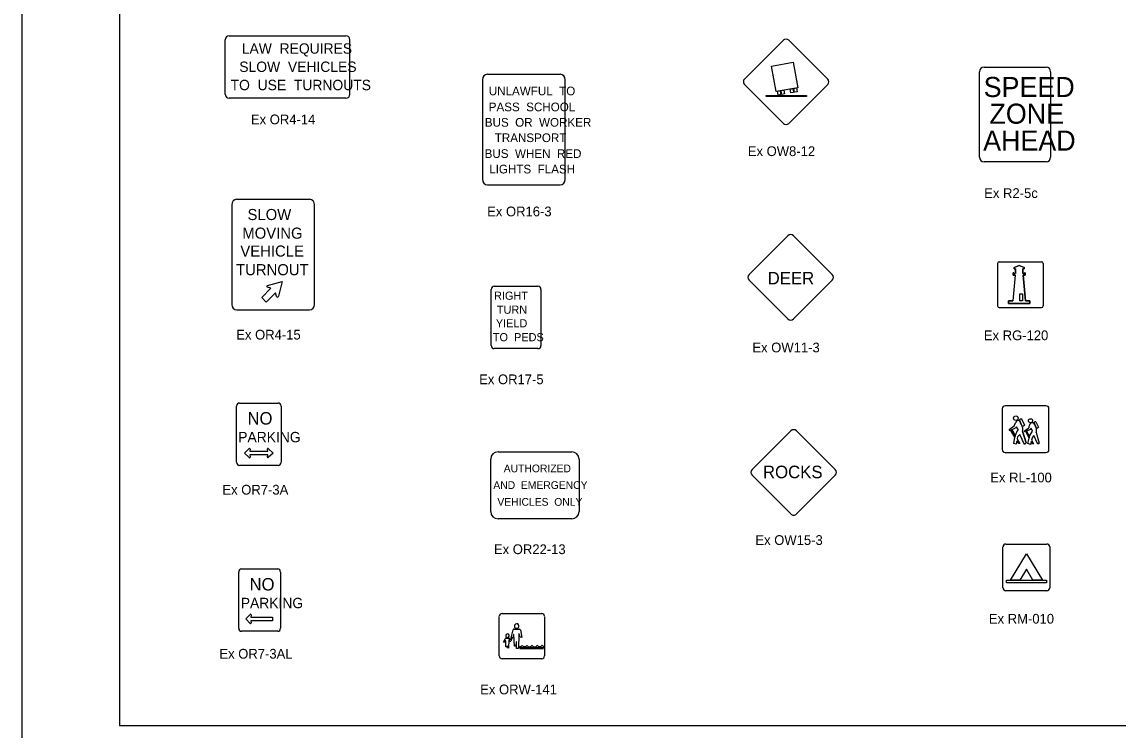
# Model space of a CAD drawing. Extents: x 42133 to 45533, y 41351 to 47951.
# Drawn here: x 42133 to 42977, y 45798 to 46343 of the extents above; entities that cross this region are included whole.
import ezdxf

# ---------------------------------------------------------------- set-up
doc = ezdxf.new("R2010")
doc.units = 0
for name, color, linetype in [('#plot_shape', 7, 'Continuous'), ('P_ODOT_PLAN_Border', 7, 'Continuous'), ('P_TRAF_SIGN_SignDetails', 7, 'Continuous')]:
    doc.layers.add(name, color=color, linetype=linetype)

msp = doc.modelspace()

# ---------------------------------------------------------------- linework, layer by layer
at = {"layer": '#plot_shape'}
msp.add_lwpolyline([(42133.34, 45751.35), (43833.34, 45751.35), (43833.34, 46851.35), (42133.34, 46851.35)], close=True, dxfattribs=at)
at = {"layer": 'P_ODOT_PLAN_Border'}
msp.add_lwpolyline([(42208.34, 45801.35), (43808.34, 45801.35), (43808.34, 46801.35), (42208.34, 46801.35)], close=True, dxfattribs=at)
at = {"layer": 'P_TRAF_SIGN_SignDetails'}
for p, q in [((42292.85, 46332.06), (42382.79, 46332.06)), ((42289.86, 46287.1), (42289.86, 46329.08)), ((42385.78, 46287.1), (42385.78, 46329.08)), ((42719.43, 46328.7), (42689.55, 46298.84)), ((42753.57, 46298.84), (42723.69, 46328.7)), ((42873.93, 46308.08), (42921.76, 46308.08)), ((42487.83, 46298.27), (42487.83, 46221.7)), ((42491.82, 46302.52), (42547.63, 46302.52)), ((42551.61, 46221.7), (42551.61, 46298.27)), ((42870.51, 46238.81), (42870.51, 46304.43)), ((42925.18, 46304.43), (42925.18, 46238.81)), ((42689.55, 46294.57), (42719.43, 46264.69)), ((42723.69, 46264.69), (42753.57, 46294.57)), ((42382.79, 46284.23), (42292.85, 46284.23)), ((42921.76, 46235.16), (42873.93, 46235.16)), ((42491.82, 46217.45), (42547.63, 46217.45)), ((42298.8, 46206.26), (42354.61, 46206.26)), ((42294.8, 46202), (42294.8, 46125.43)), ((42358.59, 46125.43), (42358.59, 46202)), ((42722.91, 46178.18), (42693.03, 46148.29)), ((42757.05, 46148.29), (42727.17, 46178.18)), ((42884.29, 46156.88), (42884.29, 46124.29)), ((42885.65, 46158.22), (42918.16, 46158.22)), ((42897.12, 46153.71), (42900.94, 46155.39)), ((42897.12, 46152.69), (42897.12, 46153.71)), ((42897.12, 46152.69), (42897.12, 46153.71)), ((42897.12, 46152.69), (42897.12, 46153.71)), ((42900.94, 46155.39), (42904.75, 46153.71)), ((42904.75, 46153.71), (42904.75, 46152.69)), ((42904.75, 46153.71), (42904.75, 46152.69)), ((42904.75, 46153.71), (42904.75, 46152.69)), ((42919.52, 46156.85), (42919.52, 46124.35)), ((42896.25, 46149.64), (42896.76, 46149.64)), ((42896.25, 46147.91), (42896.25, 46149.64)), ((42897.78, 46147.91), (42896.25, 46147.91)), ((42896.76, 46149.64), (42896.76, 46149.18)), ((42896.76, 46149.18), (42898.03, 46149.18)), ((42898.03, 46152.69), (42897.12, 46152.69)), ((42898.03, 46149.18), (42898.03, 46152.69)), ((42904.75, 46152.69), (42903.84, 46152.69)), ((42903.84, 46152.69), (42903.84, 46149.18)), ((42903.84, 46149.18), (42905.11, 46149.18)), ((42904.09, 46147.91), (42905.9, 46128.15)), ((42905.62, 46147.91), (42904.09, 46147.91)), ((42905.11, 46149.18), (42905.11, 46149.64)), ((42905.11, 46149.64), (42905.62, 46149.64)), ((42905.62, 46149.64), (42905.62, 46147.91)), ((42317.89, 46130.7), (42324.96, 46137.77)), ((42324.96, 46137.77), (42322.31, 46138.66)), ((42322.36, 46140.01), (42333.76, 46143.04)), ((42322.36, 46140.02), (42322.36, 46140.01)), ((42333.76, 46143.04), (42330.75, 46131.62)), ((42494.5, 46093.77), (42494.5, 46136.95)), ((42496.9, 46139.35), (42530.49, 46139.35)), ((42532.89, 46136.95), (42532.89, 46093.77)), ((42693.03, 46144.04), (42722.91, 46114.16)), ((42727.17, 46114.16), (42757.05, 46144.04)), ((42321.41, 46127.17), (42317.89, 46130.7)), ((42328.46, 46134.23), (42321.41, 46127.17)), ((42329.36, 46131.56), (42328.46, 46134.23)), ((42892.66, 46126.12), (42892.66, 46128.15)), ((42892.66, 46128.15), (42895.97, 46128.15)), ((42901.55, 46128.15), (42901.55, 46133.6)), ((42901.55, 46133.6), (42903.58, 46133.6)), ((42903.58, 46128.15), (42901.55, 46128.15)), ((42903.58, 46133.6), (42903.58, 46128.15)), ((42905.9, 46128.15), (42909.21, 46128.15)), ((42909.21, 46128.15), (42909.21, 46126.12)), ((42298.8, 46121.18), (42354.61, 46121.18)), ((42885.65, 46122.98), (42918.16, 46122.98)), ((42900.94, 46126.12), (42892.66, 46126.12)), ((42909.21, 46126.12), (42900.94, 46126.12)), ((42530.49, 46091.37), (42496.9, 46091.37)), ((42298.63, 46003.89), (42298.63, 46047.04)), ((42300.76, 46049.44), (42330.65, 46049.44)), ((42332.77, 46047.04), (42332.77, 46003.89)), ((42887.88, 46045.1), (42887.88, 46013.63)), ((42921.6, 46047.35), (42890.13, 46047.35)), ((42923.86, 46013.63), (42923.86, 46045.1)), ((42903.37, 46031.71), (42901.2, 46036.57)), ((42902.82, 46037.3), (42904.99, 46032.43)), ((42913.87, 46035.07), (42915.76, 46030.8)), ((42695.36, 45998.23), (42725.22, 46028.09)), ((42729.5, 46028.09), (42759.36, 45998.23)), ((42893.32, 46029.19), (42897.2, 46031.9)), ((42893.94, 46028.17), (42893.32, 46029.19)), ((42894.46, 46028.43), (42893.94, 46028.17)), ((42895.29, 46028.84), (42894.46, 46028.43)), ((42894.46, 46028.43), (42895.29, 46028.84)), ((42897.65, 46023.1), (42894.46, 46028.43)), ((42898.35, 46030.37), (42895.29, 46028.84)), ((42895.29, 46028.84), (42897.9, 46024.49)), ((42897.2, 46031.9), (42898.3, 46034.82)), ((42899, 46031.17), (42898.35, 46030.37)), ((42900.2, 46029.02), (42899, 46031.17)), ((42903.56, 46027.93), (42906.3, 46018.8)), ((42906.3, 46018.8), (42903.56, 46027.93)), ((42903.56, 46027.93), (42906.3, 46018.8)), ((42905.02, 46028.21), (42908.33, 46030.49)), ((42905.48, 46027.31), (42905.02, 46028.21)), ((42905.96, 46027.53), (42905.48, 46027.31)), ((42906.61, 46027.88), (42905.96, 46027.53)), ((42905.96, 46027.53), (42906.61, 46027.88)), ((42908.74, 46022.49), (42905.96, 46027.53)), ((42909.38, 46029.14), (42906.61, 46027.88)), ((42906.61, 46027.88), (42908.99, 46023.56)), ((42909.22, 46024.52), (42911.2, 46027.8)), ((42910.14, 46030.04), (42909.38, 46029.14)), ((42911.2, 46027.8), (42910.14, 46030.04)), ((42914.36, 46030.18), (42912.46, 46034.44)), ((42914.07, 46026.91), (42916.31, 46018.69)), ((42896.81, 46018.46), (42897.65, 46023.1)), ((42898.72, 46017.8), (42896.81, 46018.46)), ((42897.65, 46023.1), (42897.88, 46024.45)), ((42897.88, 46024.45), (42897.65, 46023.1)), ((42899.21, 46020.49), (42898.72, 46017.8)), ((42900.57, 46018.23), (42899.21, 46020.49)), ((42899.76, 46023.54), (42899.46, 46021.88)), ((42899.46, 46021.88), (42901.54, 46018.41)), ((42901.42, 46025.35), (42899.76, 46023.54)), ((42901.54, 46018.41), (42900.57, 46018.23)), ((42904.97, 46017.69), (42901.42, 46025.35)), ((42906.3, 46018.8), (42904.97, 46017.69)), ((42907.73, 46018.22), (42908.74, 46022.49)), ((42909.66, 46017.68), (42907.73, 46018.22)), ((42908.74, 46022.49), (42908.99, 46023.56)), ((42908.99, 46023.56), (42908.74, 46022.49)), ((42908.99, 46023.56), (42909.22, 46024.52)), ((42910.22, 46019.79), (42909.66, 46017.68)), ((42911.29, 46017.87), (42910.22, 46019.79)), ((42911.14, 46023.27), (42910.5, 46020.82)), ((42910.5, 46020.82), (42912.04, 46018.01)), ((42912.32, 46024.6), (42911.14, 46023.27)), ((42915.31, 46017.73), (42912.32, 46024.6)), ((42916.31, 46018.69), (42915.31, 46017.73)), ((42304.64, 46010.99), (42308.32, 46014.53)), ((42308.32, 46007.45), (42304.64, 46010.99)), ((42308.92, 46014.08), (42308.71, 46012.48)), ((42308.71, 46012.48), (42322.54, 46012.48)), ((42322.33, 46014.04), (42322.33, 46014.11)), ((42322.55, 46012.46), (42322.33, 46014.04)), ((42322.93, 46014.53), (42326.62, 46010.99)), ((42326.62, 46010.99), (42322.93, 46007.45)), ((42499.85, 46011.97), (42556.58, 46011.97)), ((42890.13, 46011.37), (42921.6, 46011.37)), ((42912.04, 46018.01), (42911.29, 46017.87)), ((42330.65, 46001.48), (42300.76, 46001.48)), ((42308.71, 46009.52), (42308.92, 46007.95)), ((42322.57, 46009.5), (42308.71, 46009.5)), ((42308.91, 46007.95), (42308.91, 46007.88)), ((42322.33, 46007.9), (42322.55, 46009.5)), ((42494.18, 45965.99), (42494.18, 46006.3)), ((42562.26, 46006.3), (42562.26, 45965.99)), ((42725.22, 45964.08), (42695.36, 45993.95)), ((42759.36, 45993.95), (42729.49, 45964.08)), ((42556.58, 45960.32), (42499.85, 45960.32)), ((42888.5, 45907.24), (42888.5, 45938.73)), ((42890.75, 45940.97), (42922.24, 45940.97)), ((42924.48, 45938.73), (42924.48, 45907.24)), ((42894.2, 45913.09), (42906.49, 45933.54)), ((42906.49, 45933.54), (42918.79, 45913.13)), ((42300.26, 45876.2), (42300.26, 45919.35)), ((42302.25, 45921.76), (42330.34, 45921.76)), ((42332.34, 45919.35), (42332.34, 45876.2)), ((42906.49, 45921.68), (42901.44, 45913.1)), ((42911.58, 45913.09), (42906.49, 45921.68)), ((42891.1, 45913.07), (42921.87, 45913.13)), ((42891.1, 45911.01), (42891.1, 45913.07)), ((42921.87, 45911.01), (42891.1, 45910.99)), ((42901.44, 45913.1), (42894.2, 45913.09)), ((42918.79, 45913.13), (42911.58, 45913.09)), ((42921.87, 45913.13), (42921.87, 45911.01)), ((42922.24, 45905), (42890.75, 45905)), ((42305.65, 45883.3), (42309.12, 45886.84)), ((42309.12, 45879.78), (42305.65, 45883.3)), ((42309.12, 45886.84), (42309.12, 45886.84)), ((42309.68, 45886.37), (42309.48, 45884.78)), ((42309.49, 45884.79), (42326.32, 45884.79)), ((42309.68, 45886.37), (42309.68, 45886.42)), ((42326.32, 45884.79), (42326.31, 45881.82)), ((42500.78, 45854.86), (42500.78, 45885.32)), ((42502.95, 45887.51), (42533.43, 45887.51)), ((42535.6, 45885.32), (42535.6, 45854.8)), ((42326.31, 45881.82), (42309.46, 45881.82)), ((42309.48, 45881.82), (42309.68, 45880.23)), ((42510.02, 45868.82), (42511.38, 45874.94)), ((42512.41, 45875.39), (42516.14, 45875.43)), ((42517.09, 45874.84), (42518.1, 45869.14)), ((42330.34, 45873.81), (42302.25, 45873.81)), ((42504.14, 45865.44), (42505.61, 45868.27)), ((42505.67, 45866.55), (42505.06, 45865.42)), ((42505.88, 45861.89), (42505.94, 45866.43)), ((42506.05, 45868.5), (42508.04, 45868.5)), ((42508.12, 45867.16), (42507.95, 45860.94)), ((42508.37, 45868.43), (42509.01, 45867.73)), ((42508.94, 45866.23), (42508.39, 45867.18)), ((42509.31, 45867.69), (42509.66, 45868.19)), ((42509.66, 45868.19), (42510.35, 45868.17)), ((42510.35, 45868.17), (42509.66, 45866.31)), ((42511.11, 45868.8), (42510.02, 45868.82)), ((42511.71, 45871.37), (42511.11, 45868.8)), ((42512.42, 45862.42), (42511.95, 45871.27)), ((42515.79, 45871.66), (42515.47, 45860.61)), ((42516.97, 45869.2), (42516.13, 45871.7)), ((42518.1, 45869.14), (42516.97, 45869.2)), ((42505.06, 45865.42), (42504.14, 45865.44)), ((42506.64, 45861.89), (42505.88, 45861.89)), ((42506.8, 45862.27), (42506.64, 45861.89)), ((42507.09, 45860.96), (42507.03, 45862.19)), ((42507.95, 45860.94), (42507.09, 45860.96)), ((42513.45, 45862.44), (42512.42, 45862.42)), ((42513.76, 45865.78), (42513.45, 45862.44)), ((42513.98, 45865.78), (42513.76, 45865.78)), ((42514.02, 45860.59), (42513.98, 45865.78)), ((42515.47, 45860.61), (42514.02, 45860.59)), ((42516.62, 45861.16), (42516.67, 45862.03)), ((42534.8, 45861.18), (42516.62, 45861.16)), ((42516.67, 45860.53), (42516.68, 45860.67)), ((42534.81, 45860.53), (42516.67, 45860.53)), ((42516.68, 45860.67), (42534.82, 45860.67)), ((42534.85, 45862.15), (42534.8, 45861.18)), ((42534.82, 45860.67), (42534.81, 45860.53)), ((42533.43, 45852.69), (42502.95, 45852.69))]:
    msp.add_line(p, q, dxfattribs=at)
for points in [[(42710.35, 46308.78), (42727.1, 46311.74), (42730.55, 46292.17), (42713.8, 46289.22)], [(42714.91, 46289.42), (42716.86, 46289.77), (42717.38, 46286.8), (42715.44, 46286.46)], [(42717.87, 46289.95), (42719.81, 46290.29), (42720.34, 46287.32), (42718.39, 46286.98)], [(42724.7, 46291.15), (42726.64, 46291.49), (42727.17, 46288.53), (42725.22, 46288.18)], [(42727.55, 46291.65), (42729.49, 46291.99), (42730.02, 46289.03), (42728.07, 46288.69)], [(42706.27, 46286.18), (42737.17, 46286.18), (42737.17, 46285.37), (42706.27, 46285.37)]]:
    msp.add_lwpolyline(points, close=True, dxfattribs=at)
for points in [[(42897.78, 46147.91), (42895.97, 46128.15), (42892.66, 46128.15), (42892.66, 46126.12), (42900.94, 46126.12), (42909.21, 46126.12), (42909.21, 46128.15), (42905.9, 46128.15), (42904.09, 46147.91), (42905.62, 46147.91), (42905.62, 46149.64), (42905.11, 46149.64), (42905.11, 46149.18), (42903.84, 46149.18), (42903.84, 46152.69), (42904.75, 46152.69), (42904.75, 46153.71), (42900.94, 46155.39), (42897.12, 46153.71), (42897.12, 46152.69), (42898.03, 46152.69), (42898.03, 46149.18), (42896.76, 46149.18), (42896.76, 46149.64), (42896.25, 46149.64), (42896.25, 46147.91), (42897.78, 46147.91)], [(42903.58, 46133.6), (42903.58, 46128.15), (42901.55, 46128.15), (42901.55, 46133.6), (42903.58, 46133.6)]]:
    msp.add_lwpolyline(points, dxfattribs=at)
for centre, radius in [((42898.38, 46037.84), 1.73), ((42909.7, 46035.85), 1.59)]:
    msp.add_circle(centre, radius, dxfattribs=at)
for centre, radius, start, end in [((42292.85, 46329.08), 2.99, 90, 180), ((42382.79, 46329.08), 2.99, 360, 90), ((42721.56, 46326.57), 3.01, 45, 135), ((42691.68, 46296.7), 3.01, 135, 225), ((42751.44, 46296.7), 3.01, 315, 45), ((42292.85, 46287.1), 2.99, 180, 270), ((42382.79, 46287.1), 2.99, 270, 360), ((42721.56, 46266.82), 3.01, 225, 315), ((42725.04, 46176.05), 3.01, 45, 135), ((42885.65, 46156.85), 1.37, 90, 180), ((42918.16, 46156.85), 1.37, 360, 90), ((42695.16, 46146.17), 3.01, 135, 225), ((42754.92, 46146.17), 3.01, 315, 45), ((42322.54, 46139.33), 0.712, 104.82648, 251.46055), ((42496.9, 46136.95), 2.4, 90, 180), ((42530.49, 46136.95), 2.4, 0, 90), ((42330.05, 46131.79), 0.712, 198.85153, 345.17352), ((42885.65, 46124.35), 1.37, 180, 270), ((42918.16, 46124.35), 1.37, 270, 0), ((42725.04, 46116.29), 3.01, 225, 315), ((42496.9, 46093.77), 2.4, 180, 270), ((42530.49, 46093.77), 2.4, 270, 0), ((42890.13, 46045.1), 2.25, 90, 180), ((42921.6, 46045.1), 2.25, 360, 90), ((42899.97, 46034.37), 1.73, 34.18469, 165.00375), ((42902.61, 46035.59), 1.72, 82.96728, 145.03271), ((42878.99, 46021.89), 26.13, 19.38191, 30.97897), ((42913.65, 46033.66), 1.42, 81.15462, 146.84538), ((42727.36, 46025.95), 3.03, 45, 135), ((42909.35, 46021.51), 11.84, 140.65318, 165.58468), ((42903.61, 46033.34), 1.64, 261.33507, 326.66493), ((42900.09, 46029.35), 3.76, 337.86939, 18.87825), ((42921.08, 46027.75), 13.04, 155.14199, 167.86112), ((42911.02, 46032.3), 1.99, 37.70509, 152.35645), ((42901.75, 46026.64), 12.84, 12.33395, 32.3878), ((42909.37, 46028.58), 4.99, 340.42764, 9.26468), ((42914.59, 46031.54), 1.39, 260.2396, 327.7604), ((42499.85, 46006.29), 5.67, 90, 180), ((42556.58, 46006.29), 5.67, 360, 90), ((42890.13, 46013.63), 2.25, 180, 270), ((42921.6, 46013.63), 2.25, 270, 0), ((42697.5, 45996.09), 3.03, 135, 224.9964), ((42757.22, 45996.09), 3.03, 315.0024, 45), ((42499.85, 45965.99), 5.67, 180, 270), ((42556.58, 45965.99), 5.67, 270, 360), ((42727.36, 45966.22), 3.03, 224.9955, 315.00225), ((42890.75, 45938.73), 2.24, 90, 180), ((42922.23, 45938.73), 2.24, 0, 90), ((42890.75, 45907.24), 2.24, 180, 270), ((42922.23, 45907.24), 2.24, 270, 0), ((42502.96, 45885.33), 2.18, 90, 180), ((42533.42, 45885.33), 2.18, 0, 90), ((42512.22, 45874.46), 0.962, 78.90199, 150.66888), ((42514.18, 45877.87), 1.78, 4.76331, 185.02535), ((42514.18, 45877.87), 1.78, 185.02535, 4.76331), ((42516.23, 45874.5), 0.933, 21.6243, 95.78963), ((42506.1, 45867.88), 0.631, 95.10828, 141.74103), ((42505.78, 45866.43), 0.158, 357.29341, 132.02448), ((42507.13, 45870.53), 1.4, 10.16903, 180.95497), ((42507.13, 45870.53), 1.4, 180.95497, 10.16903), ((42508.01, 45867.66), 0.849, 65.13306, 88.21788), ((42508.26, 45867.12), 0.142, 26.671, 160.32312), ((42509.28, 45866.5), 0.426, 217.89434, 335.59195), ((42509.19, 45867.95), 0.287, 232.06777, 293.04479), ((42511.81, 45871.27), 0.146, 4.05167, 138.88321), ((42515.96, 45871.65), 0.172, 19.64387, 173.31105), ((42506.9, 45862.18), 0.127, 0.16034, 141.65267), ((42516.55, 45864.14), 2.11, 273.33914, 331.94273), ((42520.38, 45864.26), 2.26, 209.57784, 325.21309), ((42524.11, 45864.08), 2.18, 210.75703, 330.87359), ((42527.99, 45864.07), 2.24, 207.79676, 333.04058), ((42531.86, 45864.24), 2.22, 212.25057, 327.79371), ((42535.86, 45864.46), 2.52, 213.59801, 246.52094), ((42502.96, 45854.87), 2.18, 180, 270), ((42533.42, 45854.87), 2.18, 270, 0)]:
    msp.add_arc(centre, radius, start, end, dxfattribs=at)
for centre, major_axis, ratio, start_param, end_param in [((42873.93, 46304.43), (0, 3.65), 0.9373, 0, 1.570796), ((42921.77, 46304.43), (0, 3.65), 0.9373, 4.712389, 6.283185), ((42491.82, 46298.26), (0, -4.25), 0.937267, 3.141593, 4.712389), ((42547.63, 46298.26), (0, 4.25), 0.937267, 4.712389, 6.283185), ((42873.93, 46238.8), (0, -3.65), 0.9373, 4.712389, 6.283185), ((42921.77, 46238.8), (0, 3.65), 0.9373, 3.141593, 4.712389), ((42491.82, 46221.7), (0, -4.25), 0.937267, 4.712389, 6.283185), ((42547.63, 46221.7), (0, 4.25), 0.937267, 3.141593, 4.712389), ((42298.79, 46202), (0, -4.25), 0.937267, 3.141593, 4.712389), ((42354.61, 46202), (0, 4.25), 0.937267, 4.712389, 6.283185), ((42298.79, 46125.43), (0, -4.25), 0.937267, 4.712389, 6.283185), ((42354.61, 46125.43), (0, 4.25), 0.937267, 3.141593, 4.712389), ((42300.77, 46047.04), (0, 2.4), 0.89, 0, 1.570796), ((42330.64, 46047.04), (0, 2.4), 0.89, 4.712389, 6.283185), ((42308.54, 46014.08), (0, 0.541), 0.712, 4.711817, 6.884664), ((42322.7, 46014.11), (0, 0.525), 0.712, 5.624662, 7.869865), ((42300.77, 46003.88), (0, -2.4), 0.89, 4.712389, 6.283185), ((42308.55, 46007.87), (0, -0.525), 0.712, 5.624662, 7.869865), ((42322.71, 46007.9), (0, -0.541), 0.712, 4.711817, 6.884664), ((42330.64, 46003.88), (0, 2.4), 0.89, 3.141593, 4.712389), ((42302.26, 45919.36), (0, 2.4), 0.8365, 0, 1.570796), ((42330.34, 45919.36), (0, 2.4), 0.8365, 4.712389, 6.283185), ((42309.33, 45886.43), (0, 0.525), 0.6692, 4.696505, 6.941709), ((42302.26, 45876.21), (0, -2.4), 0.8365, 4.712389, 6.283185), ((42309.32, 45880.22), (0, -0.541), 0.6692, 5.681707, 7.854554), ((42330.34, 45876.21), (0, 2.4), 0.8365, 3.141593, 4.712389)]:
    msp.add_ellipse(centre, major_axis=major_axis, ratio=ratio, start_param=start_param, end_param=end_param, dxfattribs=at)

# ---------------------------------------------------------------- texts
for s, height, p in [('LAW  REQUIRES', 7.993, (42302.56, 46318.32)), ('SLOW  VEHICLES', 7.993, (42300.65, 46304.29)), ('TO  USE  TURNOUTS', 7.993, (42293.97, 46290.24)), ('SPEED', 15.458, (42873.62, 46284.96)), ('UNLAWFUL  TO', 6.6867, (42492.72, 46286.31)), ('PASS  SCHOOL', 6.6867, (42492.67, 46274)), ('ZONE', 15.458, (42878.07, 46264.43)), ('Ex OR4-14', 7.5, (42309.6, 46264.01)), ('BUS  OR  WORKER', 6.6867, (42489.65, 46262.15)), ('TRANSPORT', 6.687, (42497.29, 46250.3)), ('AHEAD', 15.458, (42873.23, 46243.73)), ('Ex OW8-12', 7.5, (42692.08, 46239.55)), ('BUS  WHEN  RED', 6.6867, (42489.5, 46238.1)), ('LIGHTS  FLASH', 6.6867, (42493.04, 46226.19)), ('Ex R2-5c', 7.5, (42874.05, 46207.28)), ('SLOW', 8.549, (42306.98, 46190.29)), ('Ex OR16-3', 7.5, (42491.45, 46193.17)), ('MOVING', 8.549, (42303, 46175.95)), ('VEHICLE', 8.549, (42301.46, 46162.16)), ('TURNOUT', 8.549, (42298.18, 46147.83)), ('DEER', 9.656, (42707.32, 46140.76)), ('RIGHT', 6.275, (42496.75, 46128.96)), ('TURN', 6.275, (42498.92, 46118.19)), ('YIELD', 6.275, (42498.14, 46107.71)), ('Ex OR4-15', 7.5, (42298.31, 46098.34)), ('TO  PEDS', 6.275, (42495.84, 46097.03)), ('Ex RG-120', 7.5, (42873.77, 46097.84)), ('Ex OW11-3', 7.5, (42695.61, 46088.48)), ('Ex OR17-5', 7.5, (42485.3, 46063.98)), ('NO', 9.59, (42306.96, 46032.89)), ('PARKING', 7.979, (42299.83, 46019.28)), ('AUTHORIZED', 5.95, (42504.23, 45996.18)), ('ROCKS', 9.657, (42703.72, 45991.62)), ('Ex RL-100', 7.5, (42878.71, 45988.41)), ('Ex OR7-3A', 7.5, (42287.66, 45979.02)), ('AND  EMERGENCY', 5.9505, (42496.19, 45983.35)), ('VEHICLES  ONLY', 5.9505, (42499.31, 45970.42)), ('Ex OW15-3', 7.5, (42697.93, 45940.28)), ('Ex OR22-13', 7.5, (42496.66, 45933.21)), ('NO', 9.59, (42308.55, 45905.22)), ('PARKING', 7.979, (42301.79, 45891.6)), ('Ex RM-010', 7.5, (42877.64, 45879.73)), ('Ex OR7-3AL', 7.5, (42285.35, 45852.77)), ('Ex ORW-141', 7.5, (42486.08, 45825.3))]:
    msp.add_text(s, height=height, dxfattribs=at).set_placement(p)

doc.saveas('drawing.dxf')
